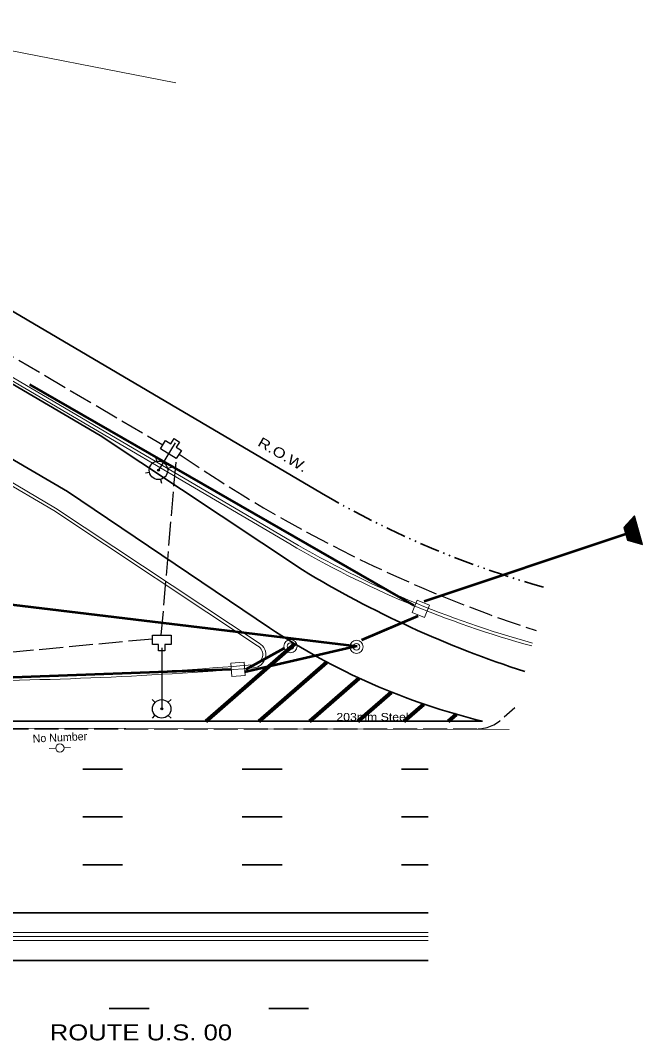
# Model space of a CAD drawing. Extents: x 168203 to 169864, y 223196 to 223870.
# Drawn here: x 168396.8 to 168443.6, y 223626.4 to 223703.1 of the extents above; entities that cross this region are included whole.
import ezdxf
from ezdxf.enums import TextEntityAlignment as Align

# ---------------------------------------------------------------- set-up
doc = ezdxf.new("R2010")
doc.units = 0
doc.header["$LTSCALE"] = 0.3
doc.header["$PDMODE"] = 32
doc.header["$PDSIZE"] = 0.15
doc.linetypes.add('DASH_DOUBLE_DOT', pattern=[9.2, 5, -1.2, 0.3, -1.2, 0.3, -1.2])
doc.linetypes.add('LONG_DASHED', pattern=[7.5, 6, -1.5])
for name, color, linetype, lineweight in [('1', 7, 'Continuous', 13), ('23', 7, 'Continuous', 25), ('32', 7, 'Continuous', 25), ('36', 7, 'Continuous', 35), ('6', 7, 'Continuous', 25), ('8', 7, 'Continuous', 25)]:
    doc.layers.add(name, color=color, linetype=linetype, lineweight=lineweight)

msp = doc.modelspace()

# ---------------------------------------------------------------- linework, layer by layer
at = {"layer": '1', "lineweight": 35}
msp.add_line((168419.4337, 223667.6033), (168370.5425, 223696.3139), dxfattribs=at)
at = {"layer": '1'}
for p, q in [((168417.0333, 223663.7944), (168368.2637, 223692.4336)), ((168417.1498, 223663.9927), (168368.3802, 223692.6319)), ((168363.6851, 223687.4684), (168399.4139, 223666.4872)), ((168363.5687, 223687.27), (168399.2919, 223666.2921)), ((168399.2919, 223666.2921), (168414.6088, 223656.1381)), ((168399.4139, 223666.4872), (168414.7358, 223656.3299)), ((168379.4515, 223634.5676), (168427.4519, 223634.5676)), ((168298.0344, 223634.2675), (168427.4519, 223634.2676)), ((168379.4515, 223633.9676), (168427.4519, 223633.9677))]:
    msp.add_line(p, q, dxfattribs=at)
for points in [[(168426.2547, 223658.6378), (168426.6305, 223659.5678), (168427.5604, 223659.1919), (168427.1846, 223658.262)], [(168412.6877, 223653.824), (168412.6123, 223654.8242), (168413.6125, 223654.8995), (168413.6879, 223653.8994)]]:
    msp.add_lwpolyline(points, close=True, dxfattribs=at)
for centre, radius in [((168417.092, 223656.1012), 0.5006), ((168417.092, 223656.1012), 0.2503), ((168422.0584, 223656.0531), 0.5006), ((168422.0584, 223656.0531), 0.2503)]:
    msp.add_circle(centre, radius, dxfattribs=at)
at = {"layer": '1', "linetype": 'DASH_DOUBLE_DOT', "lineweight": 35}
msp.add_arc((168455.0119, 223728.4674), 70.5, 239.69152, 254.72073, dxfattribs=at)
at = {"layer": '1'}
for centre, radius, start, end in [((168455.0117, 223728.4677), 75, 239.57703, 254.7212), ((168455.0117, 223728.4677), 74.77, 239.57703, 254.72118), ((168414.2295, 223655.4676), 0.77, 274.68735, 59.57703), ((168414.2295, 223655.4676), 1, 274.68735, 59.57703), ((168389.7956, 223953.4676), 299.77, 270.00005, 274.68735), ((168389.7956, 223953.4676), 300, 270.00005, 274.68735)]:
    msp.add_arc(centre, radius, start, end, dxfattribs=at)
at = {"layer": '23', "lineweight": 53}
for p, q in [((168397.459, 223675.7705), (168426.3587, 223659.1545)), ((168427.1398, 223659.4859), (168442.315, 223664.5462)), ((168380.0972, 223661.1384), (168422.0981, 223656.1092)), ((168422.4616, 223656.5749), (168426.6902, 223658.3734)), ((168413.6253, 223654.1629), (168421.9803, 223656.0948)), ((168413.7521, 223654.3671), (168416.6147, 223655.9521)), ((168388.052, 223653.4671), (168412.6271, 223654.3671))]:
    msp.add_line(p, q, dxfattribs=at)
at = {"layer": '23'}
for p, q in [((168442.9282, 223665.8587), (168443.5289, 223663.7553)), ((168442.9479, 223665.8807), (168443.5572, 223663.7471)), ((168442.237, 223665.0927), (168442.5374, 223664.0409)), ((168442.2568, 223665.1145), (168442.5657, 223664.0327)), ((168442.2765, 223665.1364), (168442.594, 223664.0246)), ((168442.2962, 223665.1583), (168442.6223, 223664.0164)), ((168442.316, 223665.1803), (168442.6507, 223664.0083)), ((168442.3357, 223665.2021), (168442.679, 223664.0001)), ((168442.3555, 223665.2239), (168442.7073, 223663.9919)), ((168442.3752, 223665.2458), (168442.7357, 223663.9838)), ((168442.3949, 223665.2678), (168442.7641, 223663.9757)), ((168442.4147, 223665.2897), (168442.7924, 223663.9675)), ((168442.4345, 223665.3115), (168442.8207, 223663.9594)), ((168442.4543, 223665.3334), (168442.849, 223663.9511)), ((168442.474, 223665.3554), (168442.8773, 223663.943)), ((168442.4937, 223665.3773), (168442.9056, 223663.9348)), ((168442.5135, 223665.3991), (168442.9339, 223663.9267)), ((168442.5332, 223665.4208), (168442.9623, 223663.9185)), ((168442.553, 223665.4428), (168442.9906, 223663.9104)), ((168442.5727, 223665.4647), (168443.019, 223663.9022)), ((168442.5925, 223665.4866), (168443.0473, 223663.8941)), ((168442.6122, 223665.5085), (168443.0757, 223663.8858)), ((168442.632, 223665.5304), (168443.104, 223663.8777)), ((168442.6517, 223665.5523), (168443.1323, 223663.8696)), ((168442.6715, 223665.5742), (168443.1606, 223663.8614)), ((168442.6912, 223665.5961), (168443.189, 223663.8532)), ((168442.711, 223665.6179), (168443.2173, 223663.8451)), ((168442.7307, 223665.6398), (168443.2456, 223663.8369)), ((168442.7504, 223665.6617), (168443.2739, 223663.8289)), ((168442.7702, 223665.6836), (168443.3023, 223663.8205)), ((168442.7899, 223665.7056), (168443.3306, 223663.8124)), ((168442.8097, 223665.7274), (168443.3588, 223663.8044)), ((168442.8294, 223665.7493), (168443.3872, 223663.7961)), ((168442.8492, 223665.7712), (168443.4156, 223663.788)), ((168442.869, 223665.7932), (168443.4439, 223663.7798)), ((168442.8887, 223665.8151), (168443.4723, 223663.7717)), ((168442.9084, 223665.8368), (168443.5006, 223663.7636)), ((168442.1976, 223665.0488), (168442.4807, 223664.0572)), ((168442.2172, 223665.0707), (168442.509, 223664.0491))]:
    msp.add_line(p, q, dxfattribs=at)
at = {"layer": '23', "lineweight": 13}
for p, q in [((168317.2096, 223650.1818), (168433.5316, 223649.8335)), ((168399.4232, 223648.4312), (168398.9238, 223648.4085)), ((168400.0476, 223648.4596), (168400.5471, 223648.4823))]:
    msp.add_line(p, q, dxfattribs=at)
msp.add_lwpolyline([(168391.8032, 223703.15), (168392.7497, 223701.5053), (168408.4668, 223698.4649)], dxfattribs=at)
at = {"layer": '23'}
msp.add_lwpolyline([(168442.1777, 223665.0269), (168442.4523, 223664.0654), (168443.5855, 223663.7391), (168442.9676, 223665.9026)], close=True, dxfattribs=at)
at = {"layer": '23', "lineweight": 13}
msp.add_circle((168399.7354, 223648.4454), 0.3125, dxfattribs=at)
at = {"layer": '23'}
msp.add_point((168442.3151, 223664.5462), dxfattribs=at)
at = {"layer": '32'}
for p, q in [((168408.406, 223671.3798), (168407.1576, 223669.3301)), ((168407.4002, 223655.9857), (168407.4002, 223651.3857))]:
    msp.add_line(p, q, dxfattribs=at)
at = {"layer": '36'}
for p, q in [((168368.071, 223692.3059), (168402.7689, 223671.93)), ((168365.5999, 223688.0978), (168400.2978, 223667.7219)), ((168402.7689, 223671.93), (168417.9879, 223661.8409)), ((168400.2978, 223667.7219), (168415.5046, 223657.4883)), ((168380.2468, 223650.4671), (168431.5307, 223650.4672)), ((168401.4521, 223646.8671), (168404.4521, 223646.8671)), ((168413.4521, 223646.8671), (168416.4521, 223646.8671)), ((168425.4521, 223646.8671), (168427.4519, 223646.8671)), ((168401.4521, 223643.2672), (168404.4521, 223643.2672)), ((168413.4521, 223643.2672), (168416.4521, 223643.2672)), ((168425.4521, 223643.2672), (168427.4519, 223643.2672)), ((168401.4521, 223639.6672), (168404.4521, 223639.6672)), ((168413.4521, 223639.6672), (168416.4521, 223639.6672)), ((168425.4521, 223639.6672), (168427.4519, 223639.6672)), ((168380.2469, 223636.0672), (168427.4519, 223636.0672)), ((168379.4521, 223632.4672), (168427.4519, 223632.4672)), ((168403.4522, 223628.8671), (168406.4522, 223628.8671)), ((168415.4522, 223628.8671), (168418.4522, 223628.8671))]:
    msp.add_line(p, q, dxfattribs=at)
at = {"layer": '36', "lineweight": 80}
for p, q in [((168410.7467, 223650.4672), (168417.413, 223656.2754)), ((168414.7282, 223650.4672), (168419.8248, 223654.9078)), ((168418.5329, 223650.4672), (168422.2479, 223653.7041)), ((168422.1722, 223650.4672), (168424.6816, 223652.6536)), ((168425.6551, 223650.4672), (168427.1252, 223651.7481)), ((168428.9889, 223650.4672), (168429.5784, 223650.9808))]:
    msp.add_line(p, q, dxfattribs=at)
at = {"layer": '36'}
for centre, radius, start, end in [((168458.9881, 223729.4434), 79.0639, 238.7636, 252.12701), ((168443.2724, 223699.0689), 49.9999, 236.26469, 256.41812)]:
    msp.add_arc(centre, radius, start, end, dxfattribs=at)
at = {"layer": '6', "linetype": 'LONG_DASHED'}
for p, q in [((168367.5642, 223694.7428), (168407.4794, 223671.2335)), ((168407.3707, 223656.9345), (168408.4991, 223670.2043)), ((168406.6999, 223656.6401), (168384.9476, 223654.5887)), ((168433.9756, 223651.4592), (168433.161, 223650.7536)), ((168332.5747, 223649.8768), (168431.2156, 223649.8769))]:
    msp.add_line(p, q, dxfattribs=at)
at = {"layer": '6'}
for points in [[(168407.6797, 223671.5553), (168408.0786, 223671.307), (168408.3269, 223671.7058), (168408.7335, 223671.4527), (168408.4852, 223671.0539), (168408.8764, 223670.8103), (168408.4991, 223670.2043), (168407.3024, 223670.9492)], [(168408.1095, 223656.2206), (168407.6396, 223656.2206), (168407.6396, 223655.7508), (168407.1607, 223655.7508), (168407.1607, 223656.2206), (168406.6999, 223656.2206), (168406.6999, 223656.9345), (168408.1095, 223656.9345)]]:
    msp.add_lwpolyline(points, close=True, dxfattribs=at)
at = {"layer": '6', "linetype": 'LONG_DASHED'}
for centre, radius, start, end in [((168468.0083, 223756.6858), 104.5726, 235.45739, 251.92502), ((168431.0019, 223652.9479), 3.0785, 273.9811, 314.53659)]:
    msp.add_arc(centre, radius, start, end, dxfattribs=at)
at = {"layer": '8'}
for p, q in [((168406.9433, 223670.3167), (168407.0111, 223670.0046)), ((168406.1885, 223669.1263), (168406.4681, 223669.1935)), ((168407.8292, 223669.4891), (168408.1365, 223669.5493)), ((168407.3067, 223668.6433), (168407.374, 223668.3638)), ((168406.6863, 223652.1041), (168406.9122, 223651.8782)), ((168407.8791, 223651.8872), (168408.105, 223652.1041)), ((168406.6954, 223650.6945), (168406.8942, 223650.9023)), ((168407.8972, 223650.8932), (168408.105, 223650.6945))]:
    msp.add_line(p, q, dxfattribs=at)
for centre in [(168407.1552, 223669.3264), (168407.4002, 223651.3857)]:
    msp.add_circle(centre, 0.6965, dxfattribs=at)
for p in [(168407.1576, 223669.3301), (168407.4002, 223651.3902)]:
    msp.add_point(p, dxfattribs=at)

# ---------------------------------------------------------------- texts
at = {"layer": '1', "width": 1.25}
msp.add_text('R.O.W.', height=0.7499, rotation=329.577, dxfattribs=at).set_placement((168416.3248, 223670.176), align=Align.CENTER)
at = {"layer": '1', "width": 1.2}
msp.add_text('ROUTE U.S. 00', height=1.202, dxfattribs=at).set_placement((168405.8363, 223626.4662), align=Align.CENTER)
at = {"layer": '23', "width": 1.15}
msp.add_text('203mm Steel', height=0.6, dxfattribs=at).set_placement((168423.2601, 223650.4818), align=Align.CENTER)
at = {"layer": '23'}
msp.add_text('No Number', height=0.6, rotation=2.6, dxfattribs=at).set_placement((168399.75, 223648.9465), align=Align.CENTER)

doc.saveas('drawing.dxf')
